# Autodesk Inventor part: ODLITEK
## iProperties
Shininess: 64.0
Length Units: 11269
Angle Units: 11279
Time Units: 11290
Mass Units: 11283
Length Display Precision: 3
Angle Display Precision: 2
Compacted: True
Part Number: ODLITEK
Document SubType Name: Modeling
Created: 2003-04
Material: Výchozí
Designer: rudolf_martonka
Density: 0.0
Volumn: 0.0
Area: 0.0
PropertySet Name: Model Information
Control State: 0
Master: False
Checked Out: False
Author: rudolf_martonka
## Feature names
1. Vysunutí1 [Extrusion]
2. Vysunutí2 [Extrusion]
3. Skořepina1
4. HranaZúžení1
5. HranaZúžení2
6. Zaoblení2 [Fillet]
